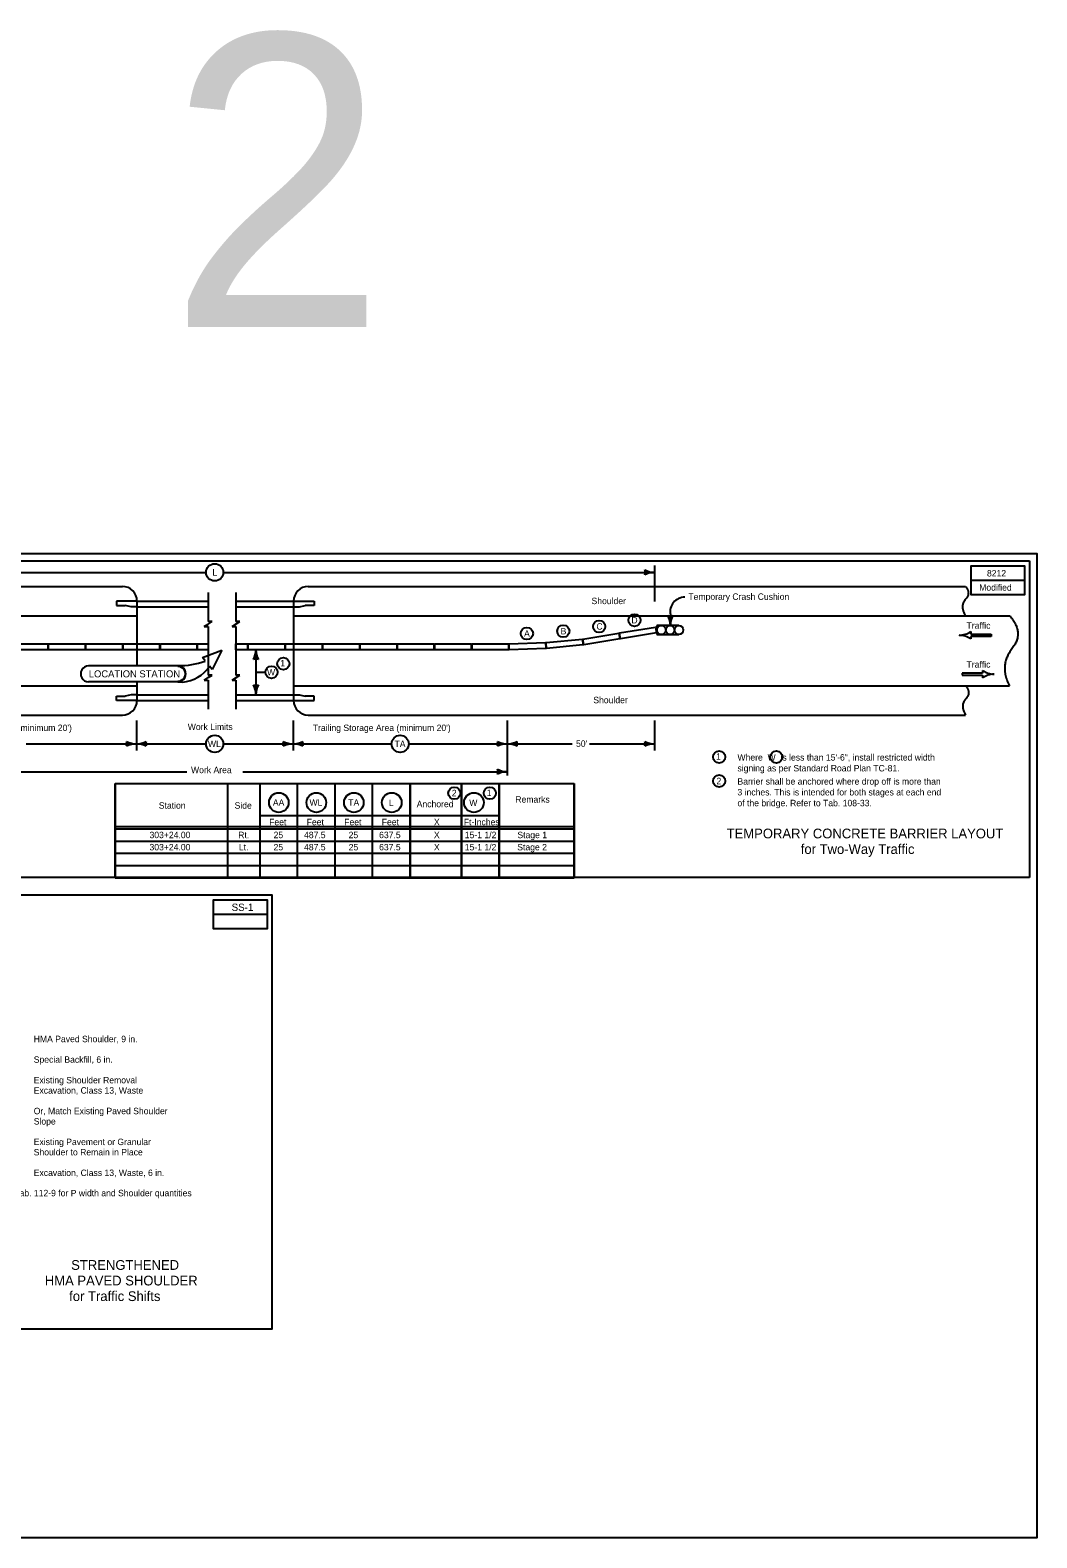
# Model space of a CAD drawing. Extents: x 10133 to 81668, y 5848 to 11018.
# Drawn here: x 14802 to 16868, y 7924 to 11018 of the extents above; entities that cross this region are included whole.
import ezdxf

# ---------------------------------------------------------------- set-up
doc = ezdxf.new("R2010")
doc.units = 0
doc.layers.add('SheetBorder', color=7, linetype='Continuous')
doc.layers.add('SheetText', color=7, linetype='Continuous')

msp = doc.modelspace()

# ---------------------------------------------------------------- linework, layer by layer
at = {"layer": 'SheetBorder'}
msp.add_lwpolyline([(13732.5, 9944), (16867.5, 9944), (16867.5, 7924), (13732.5, 7924)], close=True, dxfattribs=at)
at = {"layer": 'SheetText'}
for p, q in [((13747.5, 9929), (16852.5, 9929)), ((14230.5, 9905.4), (15163.3, 9905.4)), ((15198.3, 9905.4), (16083.2, 9905.4)), ((15211, 9905.4), (15341.5, 9905.4)), ((16083.2, 9919.2), (16083.2, 9845.6)), ((16852.5, 9929), (16852.5, 9279)), ((13862.8, 9876.4), (14991.3, 9876.4)), ((15372.7, 9876.4), (16721.1, 9876.4)), ((15021.3, 9846.4), (14979.3, 9846.4)), ((14979.3, 9846.4), (14979.3, 9837.4)), ((15021.3, 9846.4), (15167.3, 9846.4)), ((15021.3, 9846.4), (15021.3, 9713.3)), ((15167.3, 9864.4), (15167.3, 9804.5)), ((15224.4, 9864.4), (15224.4, 9804.5)), ((15224.4, 9846.4), (15342.7, 9846.4)), ((15342.7, 9846.4), (15384.7, 9846.4)), ((15342.7, 9846.4), (15342.7, 9642.4)), ((15384.7, 9846.4), (15384.7, 9837.4)), ((13779.2, 9816.4), (15021.3, 9816.4)), ((14979.3, 9837.4), (14997.3, 9837.4)), ((15009.3, 9834.4), (14997.3, 9837.4)), ((15021.3, 9834.4), (15009.3, 9834.4)), ((15021.3, 9834.4), (15167.3, 9834.4)), ((15224.4, 9834.4), (15342.7, 9834.4)), ((15342.7, 9834.4), (15354.7, 9834.4)), ((15342.7, 9816.4), (16811.5, 9816.4)), ((15354.7, 9834.4), (15366.7, 9837.4)), ((15384.7, 9837.4), (15366.7, 9837.4)), ((16115.6, 9819.1), (16115.6, 9796.6)), ((15159.3, 9794.4), (15167.3, 9799.4)), ((15159.3, 9794.4), (15167.3, 9794.4)), ((15167.3, 9799.4), (15175.3, 9804.5)), ((15175.3, 9804.5), (15167.3, 9804.5)), ((15167.3, 9794.4), (15167.3, 9744.4)), ((15216.4, 9794.4), (15232.4, 9804.5)), ((15216.4, 9794.4), (15224.4, 9794.4)), ((15232.4, 9804.5), (15224.4, 9804.5)), ((15224.4, 9794.4), (15224.4, 9744.4)), ((16087.6, 9780.2), (16087.6, 9780.2)), ((16089.4, 9783.9), (16088.1, 9783.6)), ((16133.2, 9796.2), (16088.2, 9796.2)), ((16088.2, 9796.2), (16088.2, 9778.2)), ((16088.2, 9778.2), (16133.2, 9778.2)), ((16732.2, 9783.8), (16732.2, 9778.6)), ((16732.2, 9778.6), (16773.5, 9778.6)), ((16773.5, 9778.6), (16773.5, 9774.1)), ((16708.3, 9776.3), (16708.3, 9776.3)), ((16773.5, 9774.1), (16732.2, 9774.1)), ((16732.2, 9774.1), (16732.2, 9768.8)), ((15155.5, 9730.8), (15195.7, 9745.8)), ((15161.4, 9723.5), (15155.5, 9730.8)), ((15167.3, 9744.4), (15167.3, 9694.5)), ((15195.7, 9745.8), (15175.6, 9705.8)), ((15224.4, 9744.4), (15224.4, 9694.5)), ((15265.4, 9746.4), (15265.4, 9654.4)), ((15105.2, 9713.3), (14922.1, 9713.3)), ((15105.2, 9712.4), (15105.2, 9714.2)), ((15159.3, 9684.4), (15167.3, 9689.4)), ((15167.3, 9689.4), (15175.3, 9694.5)), ((15175.3, 9694.5), (15167.3, 9694.5)), ((15175.6, 9705.8), (15169.9, 9712.8)), ((15216.4, 9684.4), (15232.4, 9694.5)), ((15232.4, 9694.5), (15224.4, 9694.5)), ((15265.4, 9700.4), (15284.7, 9700.4)), ((16755.8, 9698.7), (16714.6, 9698.7)), ((16714.6, 9698.7), (16714.6, 9694.2)), ((16714.6, 9694.2), (16755.8, 9694.2)), ((16755.8, 9704), (16755.8, 9698.7)), ((16755.8, 9694.2), (16755.8, 9689)), ((16779.8, 9696.5), (16779.8, 9696.5)), ((13779.2, 9672.4), (15021.3, 9672.4)), ((15105.2, 9680.8), (14922.1, 9680.8)), ((15009.3, 9654.4), (14997.3, 9651.4)), ((15021.3, 9654.4), (15009.3, 9654.4)), ((15021.3, 9680.8), (15021.3, 9642.4)), ((15021.3, 9654.4), (15167.3, 9654.4)), ((15105.2, 9679.9), (15105.2, 9681.7)), ((15114.7, 9680.3), (15105.2, 9679.9)), ((15159.3, 9684.4), (15167.3, 9684.4)), ((15167.3, 9684.4), (15167.3, 9624.4)), ((15216.4, 9684.4), (15224.4, 9684.4)), ((15224.4, 9684.4), (15224.4, 9624.4)), ((15224.4, 9654.4), (15342.7, 9654.4)), ((15342.7, 9672.4), (16811.5, 9672.4)), ((15342.7, 9654.4), (15354.7, 9654.4)), ((15354.7, 9654.4), (15366.7, 9651.4)), ((14979.3, 9651.4), (14997.3, 9651.4)), ((14979.3, 9642.4), (14979.3, 9651.4)), ((15021.3, 9642.4), (14979.3, 9642.4)), ((15021.3, 9642.4), (15167.3, 9642.4)), ((15224.4, 9642.4), (15342.7, 9642.4)), ((15342.7, 9642.4), (15384.7, 9642.4)), ((15384.7, 9651.4), (15366.7, 9651.4)), ((15384.7, 9642.4), (15384.7, 9651.4)), ((13862.8, 9612.4), (14991.3, 9612.4)), ((15020.1, 9601.2), (15020.1, 9539.9)), ((15341.5, 9601.2), (15341.5, 9539.9)), ((15372.7, 9612.4), (16721.1, 9612.4)), ((15781, 9601.2), (15781, 9488.8)), ((16083.2, 9601.2), (16083.2, 9539.9)), ((14794, 9553.4), (15020.1, 9553.4)), ((15020.1, 9553.4), (15163.3, 9553.4)), ((15198.3, 9553.4), (15341.5, 9553.4)), ((15211, 9553.4), (15341.5, 9553.4)), ((15341.5, 9553.4), (15543.6, 9553.4)), ((15578.9, 9553.4), (15781, 9553.4)), ((15781, 9553.4), (15914.4, 9553.4)), ((15949.7, 9553.4), (16083.2, 9553.4)), ((14532.6, 9496.3), (15123.4, 9496.3)), ((14976.8, 9472), (14976.8, 9279)), ((14976.8, 9472), (15918.4, 9472)), ((14976.8, 9279), (14976.8, 9472)), ((14976.8, 9472), (15918.4, 9472)), ((15207.8, 9279), (15207.8, 9472)), ((15238.7, 9496.3), (15781, 9496.3)), ((15240.1, 9496.3), (15341.5, 9496.3)), ((15273.8, 9279), (15273.8, 9472)), ((15350.8, 9279), (15350.8, 9472)), ((15427.8, 9279), (15427.8, 9472)), ((15504.8, 9279), (15504.8, 9472)), ((15581.8, 9279), (15581.8, 9472)), ((15581.8, 9472), (15581.8, 9279)), ((15687.4, 9279), (15687.4, 9472)), ((15687.4, 9472), (15687.4, 9279)), ((15764.4, 9279), (15764.4, 9472)), ((15764.4, 9472), (15764.4, 9279)), ((15918.4, 9279), (15918.4, 9472)), ((15918.4, 9472), (15918.4, 9279)), ((15273.8, 9406.2), (15764.4, 9406.2)), ((14976.8, 9384), (15918.4, 9384)), ((14976.8, 9379), (15918.4, 9379)), ((14976.8, 9354), (15918.4, 9354)), ((14976.8, 9329), (15918.4, 9329)), ((14976.8, 9304), (15918.4, 9304)), ((16852.5, 9279), (13747.5, 9279)), ((14976.8, 9278.7), (15918.4, 9278.7))]:
    msp.add_line(p, q, dxfattribs=at)
for points in [[(16842.5, 9919), (16842.5, 9859), (16732.5, 9859), (16732.5, 9919), (16842.5, 9919), (16842.5, 9889), (16732.5, 9889)], [(15167.3, 9746.4), (15145.8, 9746.4), (15145.8, 9758.4), (15167.3, 9758.4)], [(15167.3, 9758.4), (15167.3, 9746.4)], [(15224.4, 9746.4), (15224.4, 9758.4)], [(15224.4, 9758.4), (15248.2, 9758.4), (15248.2, 9746.4), (15224.4, 9746.4)], [(15288.3, 9233.6), (15288.3, 9173.6), (15178.3, 9173.6), (15178.3, 9233.6), (15288.3, 9233.6), (15288.3, 9203.6), (15178.3, 9203.6)]]:
    msp.add_lwpolyline(points, dxfattribs=at)
for points in [[(15935.9, 9768.6), (16009.9, 9780.7), (16011.9, 9768.9), (15937.9, 9756.7)], [(16011.4, 9781), (16085.4, 9793.1), (16087.4, 9781.3), (16013.4, 9769.1)], [(14763.3, 9758.4), (14838.3, 9758.4), (14838.3, 9746.4), (14763.3, 9746.4)], [(14839.8, 9758.4), (14914.8, 9758.4), (14914.8, 9746.4), (14839.8, 9746.4)], [(14916.3, 9758.4), (14991.3, 9758.4), (14991.3, 9746.4), (14916.3, 9746.4)], [(14992.8, 9758.4), (15067.8, 9758.4), (15067.8, 9746.4), (14992.8, 9746.4)], [(15069.3, 9758.4), (15144.3, 9758.4), (15144.3, 9746.4), (15069.3, 9746.4)], [(15249.7, 9758.4), (15324.7, 9758.4), (15324.7, 9746.4), (15249.7, 9746.4)], [(15326.2, 9758.4), (15401.2, 9758.4), (15401.2, 9746.4), (15326.2, 9746.4)], [(15402.7, 9758.4), (15477.7, 9758.4), (15477.7, 9746.4), (15402.7, 9746.4)], [(15479.2, 9758.4), (15554.2, 9758.4), (15554.2, 9746.4), (15479.2, 9746.4)], [(15555.7, 9758.4), (15630.7, 9758.4), (15630.7, 9746.4), (15555.7, 9746.4)], [(15632.2, 9758.4), (15707.2, 9758.4), (15707.2, 9746.4), (15632.2, 9746.4)], [(15708.7, 9758.4), (15783.7, 9758.4), (15783.7, 9746.4), (15708.7, 9746.4)], [(15784.7, 9758.4), (15859.7, 9761.4), (15860.2, 9749.4), (15785.2, 9746.4)], [(15860.5, 9761.4), (15935.2, 9768.5), (15936.3, 9756.5), (15861.7, 9749.4)], [(13747.5, 9243.6), (15298.3, 9243.6), (15298.3, 8352.2), (13747.5, 8352.2)]]:
    msp.add_lwpolyline(points, close=True, dxfattribs=at)
for centre, radius in [((15180.8, 9905.4), 17.6), ((16042.1, 9807.1), 12.5), ((15821.4, 9779.9), 12.5), ((15896, 9784.8), 12.5), ((15969.7, 9794.4), 12.5), ((16097.2, 9787.2), 9), ((16097.2, 9787.2), 9), ((16115.2, 9787.2), 9), ((16115.2, 9787.2), 9), ((16133.2, 9787.2), 9), ((16133.2, 9787.2), 9), ((15321.6, 9718), 12.5), ((15297.2, 9700.4), 12.5), ((15180.8, 9553.4), 17.6), ((15561.3, 9553.4), 17.6), ((16215.8, 9526.5), 12.5), ((16333.1, 9526.5), 12.5), ((16215.8, 9477.2), 12.5), ((15312.3, 9433), 20.1), ((15389.3, 9433), 20.1), ((15466.3, 9433), 20.1), ((15544.1, 9433), 20.1), ((15672.4, 9452.2), 12.5), ((15712.6, 9433), 20.1), ((15745.2, 9452.2), 12.5)]:
    msp.add_circle(centre, radius, dxfattribs=at)
for centre, radius, start, end in [((16047.5, 9905.4), 16.4, 342.2666, 17.7333), ((16083.2, 9947.9), 42.5, 241.9275, 270), ((16083.2, 9862.9), 42.5, 90, 118.0725), ((14991.3, 9846.4), 30, 0, 90), ((15372.7, 9846.4), 30, 90, 180), ((16145.1, 9824.4), 30, 90, 190.3537), ((16115.6, 9832.2), 16.4, 252.2666, 287.7334), ((16073.1, 9796.6), 42.5, 0, 28.0725), ((16158.1, 9796.6), 42.5, 151.9275, 180), ((16706.3, 9824.6), 48.4, 272.352, 302.382), ((16706.3, 9728), 48.4, 57.618, 87.648), ((15222.9, 9746.4), 42.5, 331.9275, 360), ((15265.4, 9710.8), 16.4, 72.2666, 107.7334), ((15307.9, 9746.4), 42.5, 180, 208.0725), ((16781.7, 9744.8), 48.4, 237.618, 267.648), ((16781.7, 9648.1), 48.4, 92.352, 122.382), ((15265.4, 9690.1), 16.4, 252.2666, 287.7333), ((15222.9, 9654.4), 42.5, 360, 28.0725), ((15307.9, 9654.4), 42.5, 151.9275, 180), ((14991.3, 9642.4), 30, 270, 360), ((15372.7, 9642.4), 30, 180, 270), ((14984.5, 9553.4), 16.4, 342.2666, 17.7333), ((15020.1, 9595.9), 42.5, 241.9275, 270), ((15020.1, 9510.9), 42.5, 90, 118.0725), ((15020.1, 9595.9), 42.5, 270, 298.0725), ((15020.1, 9510.9), 42.5, 61.9275, 90), ((15055.8, 9553.4), 16.4, 162.2666, 197.7334), ((15305.9, 9553.4), 16.4, 342.2666, 17.7333), ((15341.5, 9595.9), 42.5, 241.9275, 270), ((15341.5, 9510.9), 42.5, 90, 118.0725), ((15341.5, 9595.9), 42.5, 270, 298.0725), ((15341.5, 9510.9), 42.5, 61.9275, 90), ((15377.1, 9553.4), 16.4, 162.2666, 197.7334), ((15745.4, 9553.4), 16.4, 342.2666, 17.7333), ((15781, 9595.9), 42.5, 241.9275, 270), ((15781, 9510.9), 42.5, 90, 118.0725), ((15781, 9595.9), 42.5, 270, 298.0725), ((15781, 9510.9), 42.5, 61.9275, 90), ((15816.6, 9553.4), 16.4, 162.2666, 197.7334), ((16047.5, 9553.4), 16.4, 342.2666, 17.7333), ((16083.2, 9595.9), 42.5, 241.9275, 270), ((16083.2, 9510.9), 42.5, 90, 118.0725), ((15745.4, 9496.3), 16.4, 342.2666, 17.7333), ((15781, 9538.8), 42.5, 241.9275, 270), ((15781, 9453.8), 42.5, 90, 118.0725)]:
    msp.add_arc(centre, radius, start, end, dxfattribs=at)
for centre, major_axis, start_param, end_param in [((15108.1, 9870.3), (156.9, 0), 4.694293, 5.059134), ((14922.1, 9697.1), (-16.3, 0), 4.712389, 7.853982), ((15105.2, 9697.1), (16.3, 0), 4.712389, 7.853982), ((15105.2, 9697.1), (-15.4, 0), 1.570796, 4.712389), ((15110.2, 9750.6), (70.8, 0), 4.776871, 5.71778)]:
    msp.add_ellipse(centre, major_axis=major_axis, ratio=0.995025, start_param=start_param, end_param=end_param, dxfattribs=at)
for points in [[(16721.1, 9876.4), (16732.9, 9862.3), (16709.3, 9837.3), (16720.7, 9816.5)], [(16811.5, 9816.4), (16842.9, 9782), (16789.6, 9714), (16811.5, 9672.4)], [(16721.6, 9672.4), (16733.4, 9658.3), (16709.8, 9633.3), (16721.1, 9612.4)]]:
    msp.add_open_spline(points, degree=2, dxfattribs=at)

# ---------------------------------------------------------------- texts
for s, height, p in [('2', 600, (15085.9, 10409.2)), ('L', 13.2, (15176, 9898.8)), ('8212', 13.2, (16765.2, 9897)), ('Modified', 13.2, (16749.3, 9867.8)), ('Shoulder', 13.2, (15953.9, 9840.2)), ('Temporary Crash Cushion', 13.2, (16152.6, 9849)), ('D', 13.2, (16035.7, 9800.5)), ('A', 13.2, (15815.5, 9773.3)), ('B', 13.2, (15890.5, 9778.2)), ('C', 13.2, (15964, 9787.8)), ('Traffic', 13.2, (16723.3, 9789.7)), ('1', 13.2, (15315.3, 9712.4)), ('Traffic', 13.2, (16723.3, 9709.9)), ('LOCATION STATION', 14.4, (14922.5, 9689.9)), ('W', 13.2, (15288.2, 9693.8)), ('Shoulder', 13.2, (15957.6, 9636.8)), ("Approach Storage Area (minimum 20')", 13.2, (14587.1, 9579.8)), ('Work Limits', 13.2, (15125.5, 9581.8)), ("Trailing Storage Area (minimum 20')", 13.2, (15382, 9579.8)), ('WL', 13.2, (15166.9, 9546.8)), ('TA', 13.2, (15549.7, 9546.8)), ("50'", 13.2, (15922.1, 9547.4)), ('1', 13.2, (16209.5, 9520.8)), ('Where  W  is less than 15\'-6", install restricted width', 13.2, (16253.3, 9519.1)), ('Work Area', 13.2, (15132.2, 9493.3)), ('signing as per Standard Road Plan TC-81.', 13.2, (16253.3, 9496.9)), ('2', 13.2, (16210.2, 9470.6)), ('Barrier shall be anchored where drop off is more than ', 13.2, (16253.3, 9469.8)), ('AA', 13.2, (15300.1, 9426.4)), ('WL', 13.2, (15375.3, 9426.4)), ('TA', 13.2, (15454.8, 9426.4)), ('L', 13.2, (15538.2, 9426)), ('Anchored', 13.2, (15595.2, 9423.4)), ('2', 13.2, (15667.2, 9445.9)), ('W', 13.2, (15703.1, 9426)), ('1', 13.2, (15738.9, 9446.5)), ('Remarks', 13.2, (15797.5, 9432.8)), ('3 inches. This is intended for both stages at each end ', 13.2, (16253.3, 9447.6)), ('of the bridge. Refer to Tab. 108-33.', 13.2, (16253.3, 9425.4)), ('Station', 13.2, (15066.1, 9420.4)), ('Side', 13.2, (15221.6, 9420.4)), ('Feet', 13.2, (15292.5, 9386.4)), ('Feet', 13.2, (15369.5, 9386.4)), ('Feet', 13.2, (15446.5, 9386.4)), ('Feet', 13.2, (15523.5, 9386.4)), ('X', 13.2, (15630.6, 9386.4)), ('Ft-Inches', 13.2, (15691.9, 9386.4)), ('TEMPORARY CONCRETE BARRIER LAYOUT', 20, (16231.1, 9359.5)), ('303+24.00', 13.2, (15047, 9359.9)), ('303+24.00', 13.2, (15047, 9334.9)), ('Rt.', 13.2, (15229.1, 9359.9)), ('Lt.', 13.2, (15230.4, 9334.9)), ('25', 13.2, (15301.6, 9359.9)), ('25', 13.2, (15301.6, 9334.9)), ('487.5', 13.2, (15364.1, 9359.9)), ('487.5', 13.2, (15364.1, 9334.9)), ('25', 13.2, (15455.6, 9359.9)), ('25', 13.2, (15455.6, 9334.9)), ('637.5', 13.2, (15518.1, 9359.9)), ('637.5', 13.2, (15518.1, 9334.9)), ('X', 13.2, (15630.6, 9359.9)), ('X', 13.2, (15630.6, 9334.9)), ('15-1 1/2 ', 13.2, (15693.9, 9359.9)), ('15-1 1/2 ', 13.2, (15693.9, 9334.9)), ('Stage 2', 13.2, (15801.6, 9334.9)), ('Stage 1', 13.2, (15801.8, 9359.9)), ('for Two-Way Traffic', 20, (16383.2, 9327.5)), ('SS-1', 15, (15215.5, 9210.6)), ('HMA Paved Shoulder, 9 in.', 13.2, (14809.5, 8941.2)), ('Special Backfill, 6 in.', 13.2, (14809.5, 8899)), ('Existing Shoulder Removal ', 13.2, (14809.5, 8856.7)), ('Excavation, Class 13, Waste', 13.2, (14809.5, 8835.6)), ('Or, Match Existing Paved Shoulder ', 13.2, (14809.5, 8793.4)), ('Slope', 13.2, (14809.5, 8772.2)), ('Existing Pavement or Granular ', 13.2, (14809.5, 8730)), ('Shoulder to Remain in Place', 13.2, (14809.5, 8708.9)), ('Excavation, Class 13, Waste, 6 in.', 13.2, (14809.5, 8666.6)), ('Refer to Tab. 112-9 for P width and Shoulder quantities', 13.2, (14701.9, 8625)), ('STRENGTHENED ', 20, (14886.3, 8474)), ('HMA PAVED SHOULDER', 20, (14832.2, 8442)), ('for Traffic Shifts', 20, (14882.2, 8410))]:
    msp.add_text(s, height=height, dxfattribs=at).set_placement(p)

doc.saveas('drawing.dxf')
